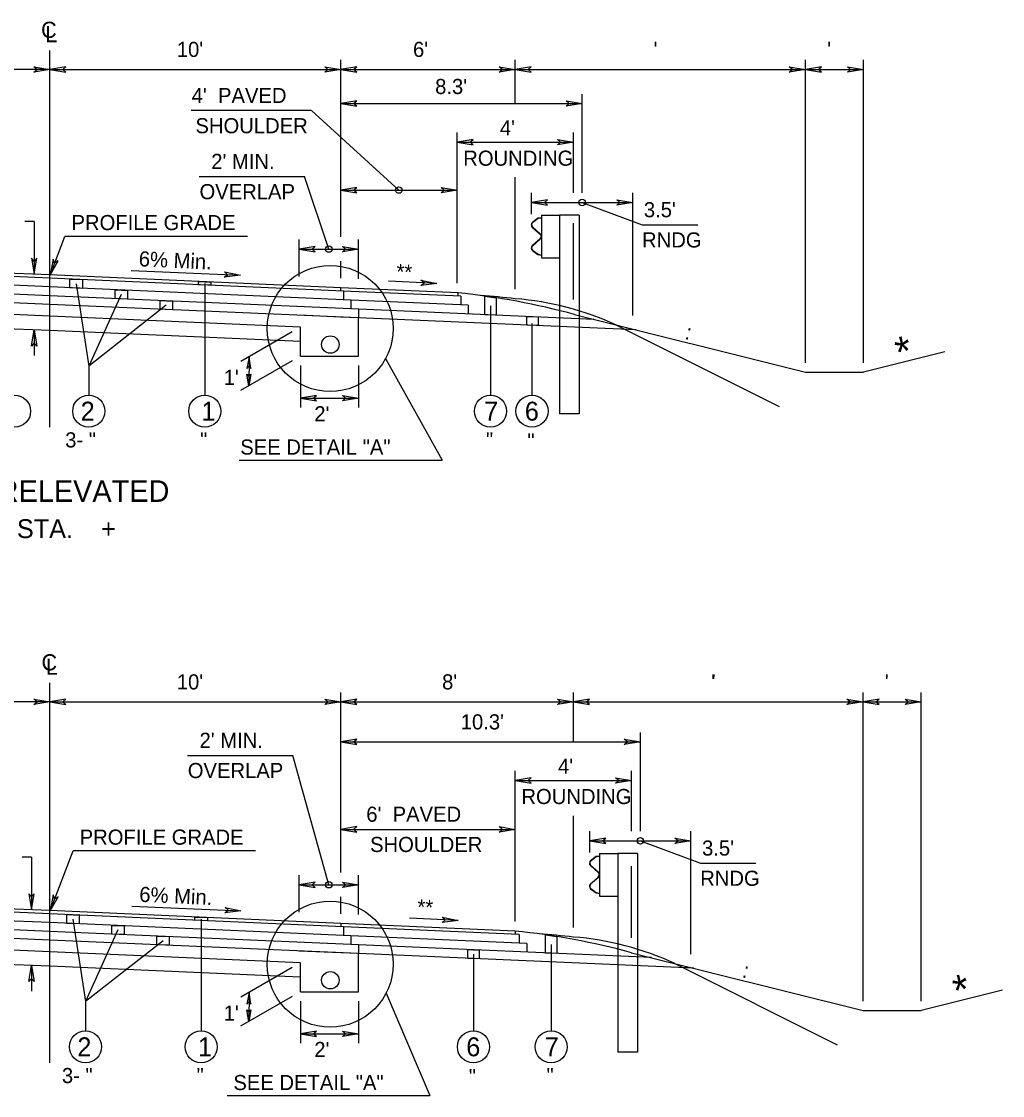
# Model space of a CAD drawing. Extents: x -592 to 1199, y -590 to 416.
# Drawn here: x 545.9 to 636.8, y 109.4 to 208.8 of the extents above; entities that cross this region are included whole.
import ezdxf

# ---------------------------------------------------------------- set-up
doc = ezdxf.new("R2010")
doc.units = 0
doc.layers.add('1', color=7, linetype='Continuous')
doc.layers.add('Des_ Drain_ Ftrs', color=7, linetype='Continuous')

msp = doc.modelspace()

# ---------------------------------------------------------------- linework, layer by layer
at = {"layer": '1'}
for p, q in [((548.542, 171.242), (548.542, 206.128)), ((575.483, 188.861), (575.483, 205.248)), ((591.648, 201.224), (591.648, 205.248)), ((618.521, 177.206), (618.521, 205.248)), ((623.909, 177.206), (623.909, 205.248)), ((548.542, 204.368), (521.601, 204.368)), ((548.542, 204.368), (575.483, 204.368)), ((575.483, 204.368), (591.648, 204.368)), ((591.648, 204.368), (618.521, 204.368)), ((618.521, 204.368), (623.909, 204.368)), ((597.844, 192.93), (597.844, 202.086)), ((575.483, 201.206), (597.844, 201.206)), ((572.754, 200.554), (561.613, 200.554)), ((580.871, 193.196), (572.757, 200.553)), ((586.259, 184.566), (586.259, 198.512)), ((597.036, 192.93), (597.036, 198.512)), ((586.259, 197.632), (597.036, 197.632)), ((562.364, 194.45), (572.128, 194.45)), ((574.382, 187.733), (572.128, 194.45)), ((591.648, 184.021), (591.648, 194.397)), ((575.483, 193.196), (586.259, 193.196)), ((593.152, 190.979), (593.152, 192.93)), ((602.536, 181.586), (602.536, 192.93)), ((593.152, 192.05), (602.536, 192.05)), ((597.844, 192.05), (603.401, 189.979)), ((547.083, 190.277), (546.203, 190.277)), ((547.083, 190.277), (547.083, 185.398)), ((593.75, 190.582), (593.233, 190.193)), ((593.762, 190.554), (593.251, 190.169)), ((594.065, 190.638), (593.75, 190.582)), ((594.065, 190.608), (593.762, 190.554)), ((594.065, 190.866), (594.065, 186.934)), ((594.065, 190.866), (595.75, 190.866)), ((595.75, 190.866), (595.75, 172.469)), ((597.575, 190.866), (595.75, 190.866)), ((597.036, 183.053), (597.036, 190.117)), ((597.575, 190.866), (597.575, 172.469)), ((603.401, 189.979), (608.556, 189.979)), ((593.218, 189.761), (593.95, 189.125)), ((593.237, 189.783), (593.969, 189.148)), ((594.035, 188.938), (594.035, 188.862)), ((594.065, 188.938), (594.065, 188.862)), ((548.551, 185.328), (549.928, 188.901)), ((566.846, 188.901), (549.928, 188.901)), ((571.639, 185.205), (571.639, 188.613)), ((577.125, 184.965), (577.125, 188.613)), ((593.95, 188.675), (593.218, 188.04)), ((593.969, 188.652), (593.237, 188.017)), ((571.639, 187.733), (577.125, 187.733)), ((593.233, 187.607), (593.75, 187.218)), ((593.251, 187.631), (593.762, 187.246)), ((593.75, 187.218), (594.065, 187.162)), ((593.762, 187.246), (594.065, 187.192)), ((594.065, 186.934), (595.75, 186.934)), ((548.542, 185.034), (521.255, 186.226)), ((548.542, 185.335), (521.594, 186.511)), ((575.483, 185.037), (575.483, 186.605)), ((548.542, 184.225), (520.332, 185.457)), ((575.488, 184.156), (548.542, 185.335)), ((575.722, 183.847), (548.542, 185.034)), ((556.079, 185.746), (566.192, 185.304)), ((548.542, 183.416), (519.41, 184.688)), ((576.426, 183.008), (548.542, 184.225)), ((550.973, 184.522), (552.137, 176.896)), ((562.881, 184.531), (562.881, 174.213)), ((575.488, 183.858), (575.488, 184.158)), ((586.365, 183.681), (575.488, 184.156)), ((584.388, 184.552), (579.894, 184.748)), ((548.542, 182.607), (519.41, 183.879)), ((577.13, 182.168), (548.542, 183.416)), ((555.149, 183.539), (552.137, 176.896)), ((575.723, 183.847), (575.723, 183.039)), ((586.593, 183.371), (575.725, 183.847)), ((576.426, 183.008), (576.426, 182.198)), ((587.288, 182.534), (576.436, 183.007)), ((586.365, 183.381), (586.365, 183.681)), ((586.593, 183.371), (586.593, 182.565)), ((548.542, 181.528), (524.798, 182.565)), ((577.13, 181.359), (548.542, 182.607)), ((559.324, 182.525), (552.137, 176.896)), ((577.13, 182.168), (577.13, 181.359)), ((598.936, 181.224), (577.147, 182.166)), ((587.288, 182.534), (587.288, 181.727)), ((589.357, 182.471), (589.357, 174.213)), ((593.152, 182.919), (593.152, 182.919)), ((548.542, 180.18), (524.798, 181.217)), ((571.741, 180.515), (548.542, 181.528)), ((575.483, 181.431), (571.644, 181.599)), ((577.13, 181.359), (575.473, 181.431)), ((577.13, 177.821), (577.13, 181.359)), ((602.839, 180.248), (577.13, 181.359)), ((597.141, 181.672), (618.521, 176.326)), ((547.083, 180.246), (547.083, 177.878)), ((571.741, 179.167), (548.542, 180.18)), ((570.979, 180.075), (566.222, 177.329)), ((571.741, 177.821), (571.741, 180.515)), ((571.741, 180.515), (571.741, 180.515)), ((593.196, 180.843), (593.196, 174.213)), ((601.036, 180.686), (616.088, 173.161)), ((631.444, 178.21), (623.909, 176.326)), ((570.979, 177.381), (566.207, 174.625)), ((566.984, 177.769), (566.963, 175.062)), ((571.741, 177.821), (577.13, 177.821)), ((579.635, 177.593), (584.862, 168.203)), ((552.137, 176.896), (552.137, 174.213)), ((571.741, 176.941), (571.741, 173.055)), ((577.13, 176.941), (577.13, 173.055)), ((618.521, 176.326), (623.909, 176.326)), ((571.741, 173.935), (577.13, 173.935)), ((597.575, 172.469), (595.75, 172.469)), ((566.076, 168.203), (584.862, 168.203)), ((548.542, 112.392), (548.542, 147.573)), ((575.483, 130.012), (575.483, 146.693)), ((597.036, 142.111), (597.036, 146.693)), ((623.861, 118.111), (623.861, 146.693)), ((629.249, 118.111), (629.249, 146.693)), ((548.542, 145.813), (521.601, 145.813)), ((548.542, 145.813), (575.483, 145.813)), ((575.483, 145.813), (597.036, 145.813)), ((597.036, 145.813), (623.861, 145.813)), ((623.861, 145.813), (629.249, 145.813)), ((603.234, 133.835), (603.234, 142.991)), ((575.484, 142.111), (603.234, 142.111)), ((561.279, 140.857), (571.043, 140.857)), ((574.382, 128.883), (571.043, 140.857)), ((591.648, 125.481), (591.648, 139.417)), ((602.424, 133.835), (602.424, 139.417)), ((591.648, 138.537), (602.424, 138.537)), ((597.036, 124.926), (597.036, 135.267)), ((575.483, 134.013), (591.648, 134.013)), ((598.542, 131.884), (598.542, 133.835)), ((607.926, 122.471), (607.926, 133.835)), ((598.542, 132.955), (607.926, 132.955)), ((603.234, 132.955), (608.791, 130.884)), ((546.847, 131.438), (545.967, 131.438)), ((546.847, 131.438), (546.847, 126.559)), ((548.551, 126.479), (550.682, 132.008)), ((567.6, 132.008), (550.682, 132.008)), ((599.14, 131.487), (598.622, 131.098)), ((599.152, 131.459), (598.64, 131.074)), ((599.454, 131.543), (599.14, 131.487)), ((599.454, 131.513), (599.152, 131.459)), ((599.454, 131.771), (599.454, 127.839)), ((599.454, 131.771), (601.139, 131.771)), ((601.139, 131.771), (601.139, 113.374)), ((602.965, 131.771), (601.139, 131.771)), ((602.965, 131.771), (602.965, 113.374)), ((598.608, 130.666), (599.339, 130.03)), ((598.627, 130.688), (599.358, 130.053)), ((602.424, 123.958), (602.424, 130.606)), ((608.791, 130.884), (613.946, 130.884)), ((571.639, 126.355), (571.639, 129.763)), ((577.125, 126.115), (577.125, 129.763)), ((599.339, 129.58), (598.608, 128.945)), ((599.358, 129.557), (598.627, 128.922)), ((599.425, 129.843), (599.425, 129.767)), ((599.454, 129.843), (599.454, 129.767)), ((571.639, 128.883), (577.125, 128.883)), ((598.622, 128.512), (599.14, 128.123)), ((598.64, 128.536), (599.152, 128.151)), ((548.542, 126.185), (521.255, 127.376)), ((548.542, 126.485), (521.594, 127.661)), ((575.483, 126.187), (575.483, 127.755)), ((599.14, 128.123), (599.454, 128.067)), ((599.152, 128.151), (599.454, 128.097)), ((599.454, 127.839), (601.139, 127.839)), ((548.542, 125.376), (520.332, 126.607)), ((575.488, 125.307), (548.542, 126.485)), ((556.128, 126.912), (566.241, 126.47)), ((548.542, 124.566), (519.41, 125.838)), ((575.722, 124.998), (548.542, 126.185)), ((576.426, 124.158), (548.542, 125.376)), ((550.668, 125.688), (551.832, 118.062)), ((562.554, 125.7), (562.554, 115.363)), ((591.648, 124.601), (575.488, 125.307)), ((575.488, 125.307), (575.488, 125.007)), ((586.359, 125.579), (581.865, 125.775)), ((548.542, 123.757), (519.41, 125.029)), ((577.13, 123.318), (548.542, 124.566)), ((554.844, 124.705), (551.832, 118.062)), ((592.01, 124.287), (575.722, 124.998)), ((575.723, 124.998), (575.723, 124.189)), ((591.648, 124.601), (591.648, 124.301)), ((548.542, 122.679), (524.798, 123.715)), ((577.13, 122.509), (548.542, 123.757)), ((559.019, 123.691), (551.832, 118.062)), ((592.705, 123.447), (576.426, 124.158)), ((576.426, 124.158), (576.426, 123.349)), ((577.13, 123.318), (577.13, 122.509)), ((604.257, 122.134), (577.13, 123.318)), ((592.01, 124.287), (592.01, 123.478)), ((592.705, 123.447), (592.705, 122.638)), ((594.968, 123.35), (594.968, 115.363)), ((598.542, 123.824), (598.542, 123.824)), ((548.542, 121.331), (524.798, 122.367)), ((571.741, 121.666), (548.542, 122.679)), ((575.483, 122.581), (571.644, 122.749)), ((577.13, 122.509), (575.484, 122.581)), ((577.13, 118.971), (577.13, 122.509)), ((608.179, 121.153), (577.13, 122.509)), ((587.772, 122.447), (587.772, 115.363)), ((602.424, 122.592), (623.861, 117.231)), ((546.847, 121.406), (546.847, 119.038)), ((571.741, 120.317), (548.542, 121.331)), ((571.741, 118.971), (571.741, 121.665)), ((571.741, 121.665), (571.741, 121.665)), ((606.426, 121.591), (621.477, 114.066)), ((570.979, 121.225), (566.222, 118.479)), ((570.979, 118.531), (566.207, 115.776)), ((566.984, 118.919), (566.963, 116.212)), ((571.741, 118.971), (577.13, 118.971)), ((579.683, 118.835), (583.738, 109.37)), ((636.784, 119.115), (629.249, 117.231)), ((551.832, 118.062), (551.832, 115.363)), ((571.741, 118.091), (571.741, 114.205)), ((577.13, 118.091), (577.13, 114.205)), ((623.861, 117.231), (629.249, 117.231)), ((571.741, 115.085), (577.13, 115.085)), ((602.965, 113.374), (601.139, 113.374)), ((564.952, 109.37), (583.738, 109.37))]:
    msp.add_line(p, q, dxfattribs=at)
for points in [[(550.4, 184.953), (551.547, 184.903), (551.547, 184.094), (550.4, 184.144)], [(554.575, 183.962), (555.722, 183.912), (555.722, 183.102), (554.575, 183.153)], [(562.307, 184.733), (563.454, 184.683), (563.454, 184.383), (562.307, 184.433)], [(558.751, 182.97), (559.897, 182.92), (559.897, 182.111), (558.751, 182.161)], [(588.835, 183.381), (589.878, 183.226), (589.878, 181.615), (588.835, 181.66)], [(592.714, 181.497), (593.757, 181.452), (593.757, 180.644), (592.714, 180.689)], [(550.095, 126.117), (551.242, 126.067), (551.242, 125.258), (550.095, 125.308)], [(561.98, 125.897), (563.127, 125.847), (563.127, 125.548), (561.98, 125.598)], [(554.271, 125.125), (555.417, 125.075), (555.417, 124.266), (554.271, 124.316)], [(558.446, 124.134), (559.593, 124.084), (559.593, 123.275), (558.446, 123.325)], [(594.447, 124.253), (595.49, 124.093), (595.49, 122.516), (594.447, 122.562)], [(587.251, 122.876), (588.294, 122.831), (588.294, 122.022), (587.251, 122.067)]]:
    msp.add_lwpolyline(points, close=True, dxfattribs=at)
for centre, radius in [((580.871, 193.196), 0.3), ((597.844, 192.05), 0.3), ((574.382, 187.733), 0.3), ((574.504, 180.379), 5.838), ((574.516, 178.892), 0.808), ((545.271, 172.727), 1.485), ((552.137, 172.727), 1.485), ((562.881, 172.727), 1.485), ((589.357, 172.727), 1.485), ((593.196, 172.727), 1.485), ((603.234, 132.955), 0.3), ((574.382, 128.883), 0.3), ((574.504, 121.529), 5.838), ((574.516, 120.042), 0.808), ((551.832, 113.878), 1.485), ((562.554, 113.878), 1.485), ((587.772, 113.878), 1.485), ((594.968, 113.878), 1.485)]:
    msp.add_circle(centre, radius, dxfattribs=at)
for centre, radius, start, end in [((593.401, 189.971), 0.278, 126.97989, 229.02099), ((593.401, 189.971), 0.249, 126.97989, 229.02099), ((593.787, 188.938), 0.249, 0, 49.03649), ((593.787, 188.938), 0.278, 0, 49.03649), ((593.401, 187.829), 0.278, 130.97902, 233.02011), ((593.401, 187.829), 0.249, 130.97902, 233.02011), ((593.787, 188.862), 0.249, 310.96352, 0), ((593.787, 188.862), 0.278, 310.96352, 0), ((579.48, 116.847), 67.188, 74.76019, 84.11876), ((580.83, 82.476), 101.244, 83.86333, 85.67746), ((589.53, 155.854), 27.368, 65.13739, 85.55132), ((598.79, 130.876), 0.278, 126.97989, 229.02099), ((598.79, 130.876), 0.249, 126.97989, 229.02099), ((599.176, 129.843), 0.249, 0, 49.03649), ((599.176, 129.767), 0.249, 310.96352, 0), ((599.176, 129.843), 0.278, 0, 49.03649), ((599.176, 129.767), 0.278, 310.96352, 0), ((598.79, 128.734), 0.278, 130.97902, 233.02011), ((598.79, 128.734), 0.249, 130.97902, 233.02011), ((584.763, 57.767), 67.188, 74.76019, 84.11876), ((586.219, 23.381), 101.244, 83.86333, 85.67746), ((594.919, 96.759), 27.368, 65.13739, 85.55132)]:
    msp.add_arc(centre, radius, start, end, dxfattribs=at)
at = {"layer": 'Des_ Drain_ Ftrs'}
for points in [[(548.542, 204.368), (547.053, 204.12), (547.348, 204.368), (547.053, 204.616)], [(548.542, 204.368), (550.03, 204.12), (549.735, 204.368), (550.03, 204.616)], [(575.483, 204.368), (573.994, 204.12), (574.289, 204.368), (573.994, 204.616)], [(575.483, 204.368), (576.971, 204.12), (576.676, 204.368), (576.971, 204.616)], [(591.648, 204.368), (590.159, 204.12), (590.454, 204.368), (590.159, 204.616)], [(591.648, 204.368), (593.136, 204.12), (592.841, 204.368), (593.136, 204.616)], [(618.521, 204.368), (617.033, 204.12), (617.328, 204.368), (617.033, 204.616)], [(618.521, 204.368), (620.01, 204.12), (619.715, 204.368), (620.01, 204.616)], [(623.909, 204.368), (622.421, 204.12), (622.716, 204.368), (622.421, 204.616)], [(575.483, 201.206), (576.971, 200.958), (576.676, 201.206), (576.971, 201.454)], [(597.844, 201.206), (596.356, 200.958), (596.651, 201.206), (596.356, 201.454)], [(586.259, 197.632), (587.748, 197.384), (587.453, 197.632), (587.748, 197.881)], [(597.036, 197.632), (595.548, 197.384), (595.843, 197.632), (595.548, 197.881)], [(575.483, 193.196), (576.971, 192.948), (576.676, 193.196), (576.971, 193.444)], [(586.259, 193.196), (584.771, 192.948), (585.066, 193.196), (584.771, 193.444)], [(593.152, 192.05), (594.641, 191.802), (594.346, 192.05), (594.641, 192.298)], [(602.536, 192.05), (601.048, 191.802), (601.343, 192.05), (601.048, 192.298)], [(571.639, 187.733), (573.127, 187.485), (572.832, 187.733), (573.127, 187.981)], [(577.125, 187.733), (575.636, 187.485), (575.931, 187.733), (575.636, 187.981)], [(547.083, 185.398), (547.332, 186.887), (547.083, 186.592), (546.835, 186.887)], [(548.551, 185.328), (549.316, 186.629), (548.978, 186.443), (548.852, 186.807)], [(566.192, 185.304), (564.694, 185.121), (565, 185.356), (564.716, 185.617)], [(584.388, 184.552), (582.89, 184.367), (583.196, 184.603), (582.912, 184.863)], [(547.083, 180.246), (547.332, 178.758), (547.083, 179.053), (546.835, 178.758)], [(566.984, 177.769), (566.795, 176.685), (566.978, 176.899), (567.157, 176.682)], [(566.963, 175.062), (566.791, 176.148), (566.97, 175.932), (567.153, 176.146)], [(571.741, 173.935), (573.23, 173.686), (572.935, 173.935), (573.23, 174.183)], [(577.13, 173.935), (575.641, 173.686), (575.936, 173.935), (575.641, 174.183)], [(548.542, 145.813), (547.053, 145.565), (547.348, 145.813), (547.053, 146.062)], [(548.542, 145.813), (550.03, 145.565), (549.735, 145.813), (550.03, 146.062)], [(575.483, 145.813), (573.994, 145.565), (574.289, 145.813), (573.994, 146.062)], [(575.483, 145.813), (576.971, 145.565), (576.676, 145.813), (576.971, 146.062)], [(597.036, 145.813), (595.547, 145.565), (595.842, 145.813), (595.547, 146.062)], [(597.036, 145.813), (598.524, 145.565), (598.229, 145.813), (598.524, 146.062)], [(623.861, 145.813), (622.373, 145.565), (622.668, 145.813), (622.373, 146.062)], [(623.861, 145.813), (625.35, 145.565), (625.055, 145.813), (625.35, 146.062)], [(629.249, 145.813), (627.761, 145.565), (628.056, 145.813), (627.761, 146.062)], [(575.484, 142.111), (576.972, 141.863), (576.677, 142.111), (576.972, 142.36)], [(603.234, 142.111), (601.745, 141.863), (602.04, 142.111), (601.745, 142.36)], [(591.648, 138.537), (593.136, 138.289), (592.841, 138.537), (593.136, 138.786)], [(602.424, 138.537), (600.936, 138.289), (601.231, 138.537), (600.936, 138.786)], [(575.483, 134.013), (576.971, 133.765), (576.676, 134.013), (576.971, 134.261)], [(591.648, 134.013), (590.159, 133.765), (590.454, 134.013), (590.159, 134.261)], [(598.542, 132.955), (600.03, 132.707), (599.735, 132.955), (600.03, 133.204)], [(607.926, 132.955), (606.437, 132.707), (606.732, 132.955), (606.437, 133.204)], [(571.639, 128.883), (573.127, 128.635), (572.832, 128.883), (573.127, 129.132)], [(577.125, 128.883), (575.636, 128.635), (575.931, 128.883), (575.636, 129.132)], [(546.847, 126.559), (547.096, 128.047), (546.847, 127.752), (546.599, 128.047)], [(548.551, 126.479), (549.316, 127.779), (548.978, 127.593), (548.852, 127.957)], [(566.241, 126.47), (564.743, 126.287), (565.049, 126.522), (564.765, 126.783)], [(586.359, 125.579), (584.861, 125.395), (585.167, 125.63), (584.882, 125.891)], [(546.847, 121.406), (547.096, 119.918), (546.847, 120.213), (546.599, 119.918)], [(566.984, 118.919), (566.795, 117.835), (566.978, 118.049), (567.157, 117.832)], [(566.963, 116.212), (566.791, 117.299), (566.97, 117.082), (567.153, 117.296)], [(571.741, 115.085), (573.23, 114.837), (572.935, 115.085), (573.23, 115.333)], [(577.13, 115.085), (575.641, 114.837), (575.936, 115.085), (575.641, 115.333)]]:
    msp.add_lwpolyline(points, close=True, dxfattribs=at)

# ---------------------------------------------------------------- texts
at = {"layer": '1'}
for s, height, p in [("10'", 1.4, (560.297, 205.519)), ("6'", 1.4, (582.175, 205.519)), ("  '", 1.4, (603.422, 205.519)), (" '", 1.4, (620.02, 205.519)), ("8.3'", 1.4, (584.227, 202.087)), ("4'  PAVED", 1.4, (561.673, 201.254)), ('SHOULDER', 1.4, (562.022, 198.454)), ("4'", 1.4, (590.219, 198.248)), ("2' MIN.", 1.4, (563.486, 195.15)), ('ROUNDING', 1.4, (586.83, 195.448)), ('OVERLAP', 1.4, (562.397, 192.35)), ("3.5'", 1.4, (603.561, 190.679)), ('PROFILE GRADE', 1.4, (550.54, 189.486)), ('RNDG', 1.4, (603.391, 187.879)), ('2', 1.75, (551.39, 171.852)), ('1', 1.75, (562.579, 171.853)), ("2'", 1.4, (573.033, 171.783)), ('7', 1.75, (588.766, 171.853)), ('6', 1.75, (592.532, 171.853)), ('3- "', 1.4, (549.958, 169.368)), (' "', 1.4, (561.937, 169.368)), ('SEE DETAIL "A"', 1.4, (566.174, 168.706)), (' "', 1.4, (588.413, 169.368)), (' "', 1.4, (592.253, 169.272)), ('SUPERELEVATED', 2, (536.422, 164.329)), ('STA.    +      TO STA.    +     ', 1.75, (528.512, 160.973)), ("10'", 1.4, (560.297, 146.965)), ("8'", 1.4, (584.869, 146.965)), ("  '", 1.4, (608.752, 146.965)), ("  '", 1.4, (608.81, 146.965)), (" '", 1.4, (625.36, 146.965)), ("10.3'", 1.4, (586.597, 143.262)), ("2' MIN.", 1.4, (562.401, 141.557)), ("4'", 1.4, (595.607, 139.153)), ('OVERLAP', 1.4, (561.312, 138.757)), ('ROUNDING', 1.4, (592.218, 136.353)), ("6'  PAVED", 1.4, (577.849, 134.713)), ('PROFILE GRADE', 1.4, (551.295, 132.593)), ('SHOULDER', 1.4, (578.198, 131.913)), ("3.5'", 1.4, (608.95, 131.584)), ('RNDG', 1.4, (608.78, 128.784)), ('2', 1.75, (551.085, 113.003)), ('1', 1.75, (562.252, 113.003)), ("2'", 1.4, (573.033, 112.934)), ('6', 1.75, (587.107, 113.003)), ('7', 1.75, (594.377, 113.003)), ('3- "', 1.4, (549.653, 110.518)), (' "', 1.4, (561.61, 110.518)), (' "', 1.4, (586.828, 110.422)), (' "', 1.4, (594.025, 110.518)), ('SEE DETAIL "A"', 1.4, (565.537, 109.874))]:
    msp.add_text(s, height=height, dxfattribs=at).set_placement(p)
for s, height, rotation, p in [('6% Min.', 1.4, 357.37265, (556.748, 186.145)), ('**', 1.4, 357.21663, (580.603, 184.957)), (' : ', 1.4, 345.77179, (606.782, 179.552)), ('*', 2.8, 12.84793, (627.224, 176.731)), ("1'", 1.4, 0.14377, (564.637, 175.152)), ('6% Min.', 1.4, 357.37313, (556.797, 127.31)), ('**', 1.4, 357.21679, (582.545, 126.14)), (' : ', 1.4, 345.77179, (612.093, 120.464)), ('*', 2.8, 12.84793, (632.565, 117.637)), ("1'", 1.4, 0.14377, (564.637, 116.302))]:
    msp.add_text(s, height=height, rotation=rotation, dxfattribs=at).set_placement(p)
at = {"layer": 'Des_ Drain_ Ftrs'}
for s, p in [('C', (547.719, 207.281)), ('L', (548.113, 206.883)), ('C', (547.761, 148.723)), ('L', (548.155, 148.326))]:
    msp.add_text(s, height=1.5, dxfattribs=at).set_placement(p)

doc.saveas('drawing.dxf')
